// Mitsubishi GX Works2 project: sample_melsec_test   PLC: Q06UDV

PROGRAM MAIN
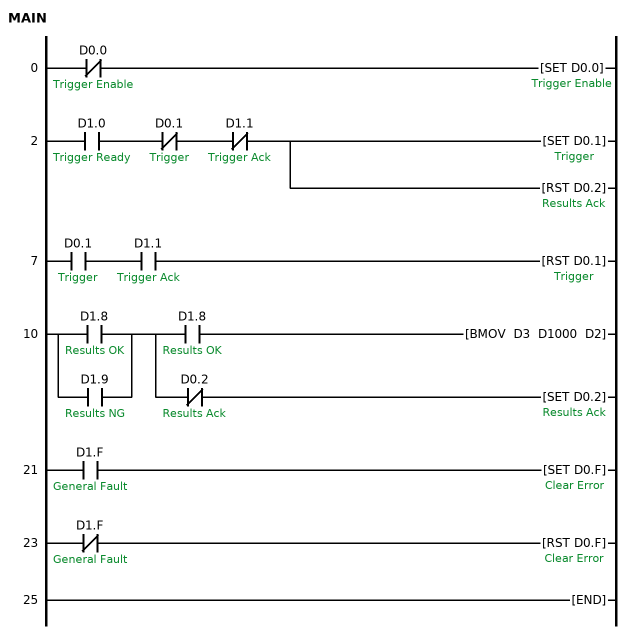
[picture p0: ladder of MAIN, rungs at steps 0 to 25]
0     LDI     D0.0  ; Trigger Enable
      SET     D0.0  ; Trigger Enable
2     LD      D1.0  ; Trigger Ready
      ANI     D0.1  ; Trigger
      ANI     D1.1  ; Trigger Ack
      SET     D0.1  ; Trigger
      RST     D0.2  ; Results Ack
7     LD      D0.1  ; Trigger
      AND     D1.1  ; Trigger Ack
      RST     D0.1  ; Trigger
10    LD      D1.8  ; Results OK
      OR      D1.9  ; Results NG
      MPS
      AND     D1.8  ; Results OK
      BMOV    D3 D1000 D2
      MPP
      ANI     D0.2  ; Results Ack
      SET     D0.2  ; Results Ack
21    LD      D1.F  ; General Fault
      SET     D0.F  ; Clear Error
23    LDI     D1.F  ; General Fault
      RST     D0.F  ; Clear Error
25    END
END_PROGRAM

// device comments not shown above
D0  ; Control
D1  ; Status
